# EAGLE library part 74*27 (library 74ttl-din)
Triple 3-input NOR gate
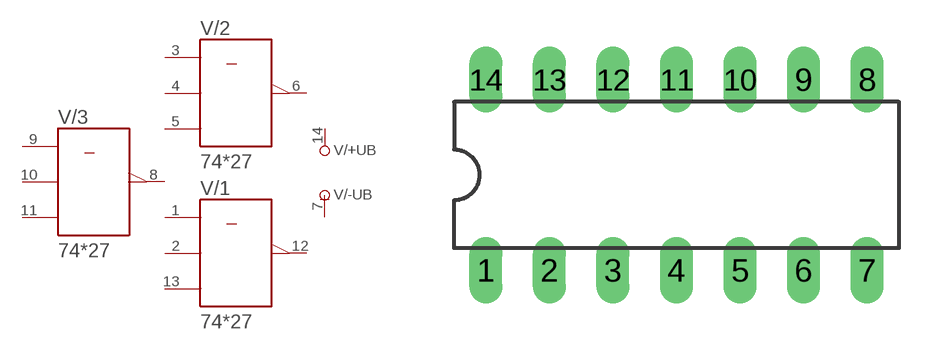
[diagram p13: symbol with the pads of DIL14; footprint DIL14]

Designator prefix V; gates /+UB=+UB /-UB=-UB /1=27 /2=27 /3=27

## 7427N  [DIL14]
1  /1:A  in
2  /1:B  in
3  /2:A  in
4  /2:B  in
5  /2:C  in
6  /2:Y  out
7  /-UB:-UB  pwr
8  /3:Y  out
9  /3:A  in
10  /3:B  in
11  /3:C  in
12  /1:Y  out
13  /1:C  in
14  /+UB:+UB  pwr

## Footprint DIL14 (pad centres in mm)
Dual In Line Package
drill 0.813 long: 1 -7.62,-3.81; 2 -5.08,-3.81; 3 -2.54,-3.81; 4 0,-3.81; 5 2.54,-3.81; 6 5.08,-3.81; 7 7.62,-3.81; 8 7.62,3.81; 9 5.08,3.81; 10 2.54,3.81; 11 0,3.81; 12 -2.54,3.81; 13 -5.08,3.81; 14 -7.62,3.81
